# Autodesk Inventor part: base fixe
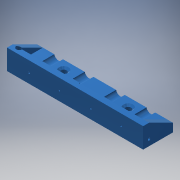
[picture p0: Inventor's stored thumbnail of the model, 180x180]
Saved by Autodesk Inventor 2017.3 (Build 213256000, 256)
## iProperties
Part Number: base fixe
Material: Plastique ABS
Document SubType Name: Modeling
Designer: ficho
Density: 1.06 g/cm^3
Appearance: Cyan
Author: ficho
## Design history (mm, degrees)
sketch "Esquisse1"
  geometry: L1 (0, 0)-(114, 0); L2 (114, 0)-(114, 25); L3 (114, 25)-(0, 25); L4 (0, 25)-(0, 0)
  constraints: 8 end point, 2 parallel, 1 horizontal, 1 perpendicular
  dimensions: "d0" = 114 distance between parallel lines of L2 L4; "d1" = 25 distance between parallel lines of L1 L3
extrude "Extrusion1" new body sketch "Esquisse1" distance "d2" = 17; taper "d3" = 0 deg
sketch "Esquisse2"
  geometry: L1 (-17, 0)-(-17, 25); L2 (-7, 25)-(-17, 5); L3 (-7, 25)-(-17, 25); L4 (-17, 25)-(-17, 5); L5 (-17, 0)-(-17, 25) reference; 1 further point
  constraints: 6 end point, 1 collinear
extrude "Extrusion2" cut sketch "Esquisse2" stored distance "d6" = 10; taper "d7" = 0 deg
sketch "Esquisse3"
  geometry: L1 (114, 25)-(0, 25) reference; L2 (5, 25)-(109, 25); L3 (109, 25)-(109, 5); L4 (109, 5)-(5, 5); L5 (5, 5)-(5, 25); L6 (114, 25)-(114, 5) reference; L7 (0, 5)-(0, 25) reference; L8 (0, 0)-(114, 0) reference
  constraints: 8 end point, 2 parallel, 1 horizontal, 1 perpendicular, 1 point on line
  dimensions: "d8" = 5 distance between parallel lines of L3 L6; "d9" = 5 distance between parallel lines of L5 L7; "d12" = 5 distance between parallel lines of L8 L4
extrude "Extrusion3" cut sketch "Esquisse3" distance "d10" = 15; taper "d11" = 0 deg
sketch "Esquisse4"
  geometry: C1 r 1.25 at (13.257, 9.146) reference; C2 r 1.25 at (38.742, 9.146) reference; C3 r 1.25 at (65.007, 9.146) reference; C4 r 1.25 at (90.492, 9.146) reference; 1 further point
hole "Perçage1" sketch "Esquisse4" at (13.257, 9.146), (38.742, 9.146), (65.007, 9.146), (90.492, 9.146) diameter "d13" = 1.5; stored, may be unused: countersink angle "d17" = 90 deg, drill point angle "d19" = 118 deg; dims "d14" = 6, "d15" = 4, "d16" = 2, "d18" = 5
sketch "Esquisse5"
  geometry: L1 (5, 5)-(5, 25) reference; L2 (109, 25)-(109, 5) reference; L3 (5, 25)-(109, 25); L4 (109, 25)-(109, 11); L5 (109, 11)-(5, 11); L6 (5, 11)-(5, 25); 1 further point
  constraints: 8 end point, 2 parallel, 1 horizontal, 1 perpendicular, 1 point on line
  dimensions: "d20" = 14 distance between parallel lines of L5 L3
node "Plan de construction1"
extrude "Extrusion4" join sketch "Esquisse5" distance "d21" = 5; taper "d22" = 0 deg
sketch "Esquisse6"
  geometry: L1 (109, -10)-(5, -10) reference; L2 (22.007, -7.854)-(22.007, -10); L3 (22.007, -10)-(14.507, -10); L4 (14.507, -10)-(14.507, -7.854); L5 (47.492, -7.854)-(47.492, -10); L6 (47.492, -10)-(39.992, -10); L7 (39.992, -10)-(39.992, -7.854); L8 (73.757, -7.854)-(73.757, -10); L9 (73.757, -10)-(66.257, -10); L10 (66.257, -10)-(66.257, -7.854); L11 (99.242, -7.854)-(99.242, -10); L12 (99.242, -10)-(91.742, -10); L13 (91.742, -10)-(91.742, -7.854); C1 r 1.25 at (18.257, -7.854) reference; C2 r 1.25 at (43.742, -7.854) reference; C3 r 1.25 at (70.007, -7.854) reference; C4 r 1.25 at (95.492, -7.854) reference; A1 r 3.75 centre (18.257, -7.854) between (22.007, -7.854) and (14.507, -7.854); A2 r 3.75 centre (43.742, -7.854) between (47.492, -7.854) and (39.992, -7.854); A3 r 3.75 centre (70.007, -7.854) between (73.757, -7.854) and (66.257, -7.854); A4 r 3.75 centre (95.492, -7.854) between (99.242, -7.854) and (91.742, -7.854); 1 further point
  constraints: 24 end point, 8 point on circle, 4 centre point, 4 coincident, 4 parallel, 4 point on line
  dimensions: "d23" = 7.5 diameter of A1; "d24" = 7.5 diameter of A2 (= d23); "d25" = 7.5 diameter of A3 (= d23); "d26" = 7.5 diameter of A4 (= d23)
extrude "Extrusion5" cut sketch "Esquisse6" stored distance "d27" = 15; taper "d28" = 0 deg
sketch "Esquisse7"
  geometry: C1 r 1 at (5, 5) reference; 1 further point
extrude "Extrusion6" cut sketch "Esquisse7" distance "d29" = 5; taper "d30" = 0 deg
sketch "Esquisse8"
  geometry: C1 r 1 at (-5, 5) reference; 1 further point
extrude "Extrusion7" cut sketch "Esquisse8" distance "d31" = 5; taper "d32" = 0 deg
sketch "Esquisse9"
  geometry: C1 r 1 at (5, 21) reference; 1 further point
hole "Perçage2" sketch "Esquisse9" at (5, 21) diameter "d33" = 1.5; stored, may be unused: countersink angle "d37" = 90 deg, drill point angle "d39" = 118 deg; dims "d34" = 6, "d35" = 4, "d36" = 2, "d38" = 5
sketch "Esquisse10"
  geometry: L1 (0, 0)-(114, 0) reference; L2 (0, 5)-(0, 25) reference; L3 (114, 25)-(114, 5) reference; 2 further points
  dimensions: "d40" = 17.5 distance from line of point (30, 17.5) L1 (= d41); "d41" = 17.5 distance from line of L1 point (84, 17.5); "d42" = 30 distance from line of point (30, 17.5) L2; "d43" = 30 distance from line of point (84, 17.5) L3 (= d42)
hole "Perçage3" sketch "Esquisse10" at (30, 17.5), (84, 17.5) diameter "d44" = 5; stored, may be unused: countersink angle "d48" = 90 deg, drill point angle "d50" = 118 deg; dims "d45" = 6, "d46" = 8, "d47" = 2, "d49" = 5
sketch "Esquisse11"
  geometry: L1 (109, 5)-(5, 5) reference; C1 r 1 at (57, 5); 1 further point
  constraints: 1 centre point, 1 midpoint
  dimensions: "d51" = 2 diameter of C1
extrude "Extrusion8" cut sketch "Esquisse11" stored distance "d52" = 5; taper "d53" = 0 deg
sketch "Esquisse12"
  geometry: C1 r 2.5 at (5.138, 5.074); 1 further point
  constraints: 1 centre point
  dimensions: "d54" = 5 diameter of C1
extrude "Extrusion9" cut sketch "Esquisse12" stored distance "d55" = 5; taper "d56" = 0 deg
node "Solide1"
node "Référence1"
node "Référence2"
node "Référence3"
node "Référence4"
node "Référence5"
node "Référence6"
node "Référence7"
node "Référence8"
node "Référence9"
node "Référence10"
node "Référence11"
